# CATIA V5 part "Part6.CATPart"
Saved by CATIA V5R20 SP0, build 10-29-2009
Part number: 1DIN7991416_DIN 7991 - M4 x 16 --- 16C
Revision: ANY
Definition: UNKNOWN
Nomenclature: 1DIN7991416_DIN 7991 - M4 x 16 --- 16C
Source: Unknown
Bounding box of the stored display mesh (mm): x 0 to 16, y -3.633 to 3.633, z -3.82 to 3.82
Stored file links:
  C:\Users\Utente\Desktop\IO LAVORO\3D X SITO CF\CUMSA\3D files PW\pw060622\pw060622_injection\Part6.CATPart
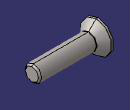
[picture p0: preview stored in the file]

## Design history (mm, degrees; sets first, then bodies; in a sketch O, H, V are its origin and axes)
Body1 "Hex" (main body)
  Solid1: solid without history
